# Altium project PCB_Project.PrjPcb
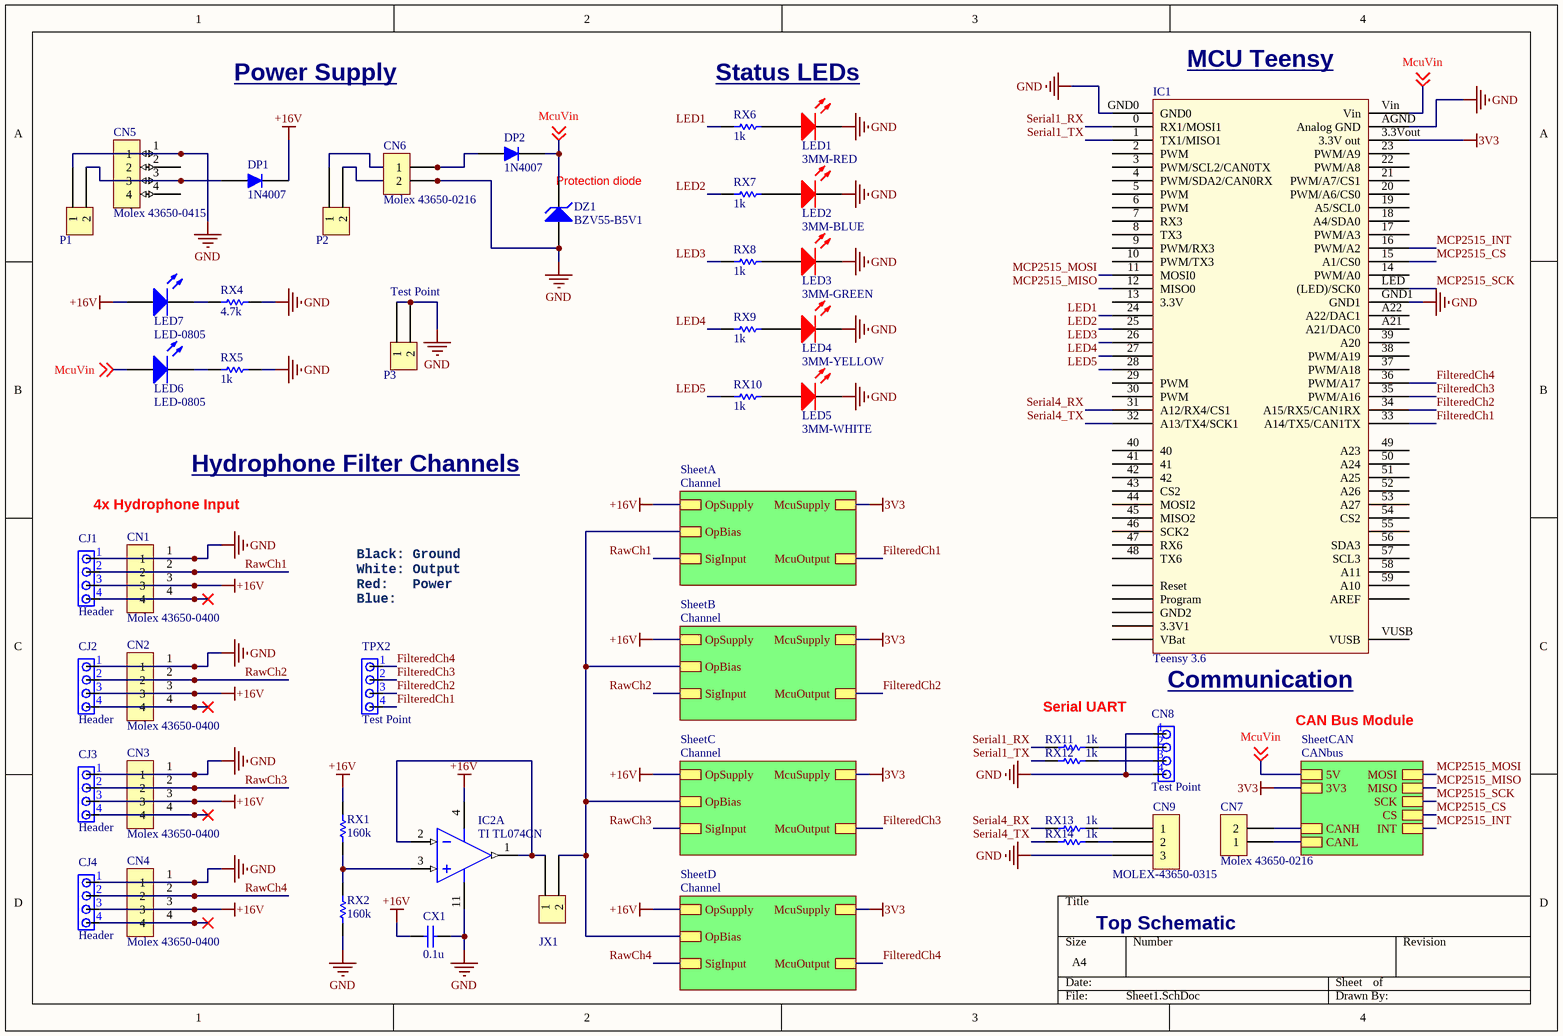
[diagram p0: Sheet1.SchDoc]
3 sheets, 286 parts. Net scope: hierarchical (ports join the sheet entries above them; power ports are global).
Sheets:
  Sheet1.SchDoc
    SheetA = Channel.SchDoc
    SheetB = Channel.SchDoc
    SheetC = Channel.SchDoc
    SheetD = Channel.SchDoc
    SheetCAN = CANbus.SchDoc

## Sheet Sheet1.SchDoc
size A4; SheetNumber: 1; SheetTotal: 3

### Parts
CJ1  Header  [PCB-0bfjvpkufifbx95u45yw-1]
CJ2  Header  [PCB-0bfjvpkufifbx95u45yw-1]
CJ3  Header  [PCB-0bfjvpkufifbx95u45yw-1]
CJ4  Header  [PCB-0bfjvpkufifbx95u45yw-1]
CN1  Molex 43650-0400  [PCB-jj5tynijxzvke4ihhisw-1]
CN2  Molex 43650-0400  [PCB-jj5tynijxzvke4ihhisw-1]
CN3  Molex 43650-0400  [PCB-jj5tynijxzvke4ihhisw-1]
CN4  Molex 43650-0400  [PCB-jj5tynijxzvke4ihhisw-1]
CN5  Molex 43650-0415  [PCB-vm2iqe32ix5ks50y5iwy-1]
CN6  Molex 43650-0216  [FP w/o mated connector outlined]
CN7  Molex 43650-0216  [FP w/o mated connector outlined]
CN8  Test Point  [PCB-0bfjvpkufifbx95u45yw-1]
CN9  MOLEX-43650-0315  [PCB-7ufjemrsb0p0f0we5rgt-1]
CX1  0.1u  [PCB-lqeomw61a722wi99q4vw-1]
DP1  1N4007  [PCBComponent_1]
DP2  1N4007  [PCBComponent_1]
DZ1  BZV55-B5V1  [PCB-lgxrfu0czqrr4p3mixw0-1]
IC1  Teensy 3.6  [PCB-6b281r67jm1h1mm3hlzb-1]
IC2  TI TL074CN  [PDIP-14]  (part A of 4)
JX1  Header 2pin  [PCB-header]  (value not drawn)
LED1  3MM-RED  [PCB-8fnm1gqdpse16arx63h0-1]
LED2  3MM-BLUE  [PCB-8fnm1gqdpse16arx63h0-1]
LED3  3MM-GREEN  [PCB-8fnm1gqdpse16arx63h0-1]
LED4  3MM-YELLOW  [PCB-8fnm1gqdpse16arx63h0-1]
LED5  3MM-WHITE  [PCB-8fnm1gqdpse16arx63h0-1]
LED6  LED-0805  [PCB-9ifma0oh53wy532w7hco-1]
LED7  LED-0805  [PCB-9ifma0oh53wy532w7hco-1]
P1  Header 2pin  [PCB-header]  (value not drawn)
P2  Header 2pin  [PCB-header]  (value not drawn)
P3  Test Point  [PCB-header]
RX1  160k  [RESC2013X70X40NL20T20]
RX2  160k  [RESC2013X70X40NL20T20]
RX4  4.7k  [RESC2013X70X40NL20T20]
RX5  1k  [RESC2013X70X40NL20T20]
RX6  1k  [RESC2013X70X40NL20T20]
RX7  1k  [RESC2013X70X40NL20T20]
RX8  1k  [RESC2013X70X40NL20T20]
RX9  1k  [RESC2013X70X40NL20T20]
RX10  1k  [RESC2013X70X40NL20T20]
RX11  1k  [RESC2013X70X40NL20T20]
RX12  1k  [RESC2013X70X40NL20T20]
RX13  1k  [RESC2013X70X40NL20T20]
RX14  1k  [RESC2013X70X40NL20T20]
TPX2  Test Point  [PCB-0bfjvpkufifbx95u45yw-1]

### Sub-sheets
SheetA = Channel: SigInput, OpSupply, OpBias, McuSupply, McuOutput
SheetB = Channel: SigInput, OpSupply, OpBias, McuSupply, McuOutput
SheetC = Channel: SigInput, OpSupply, OpBias, McuSupply, McuOutput
SheetCAN = CANbus: SCK, 3V3, CS, MISO, MOSI, 5V, CANL, CANH, INT
SheetD = Channel: SigInput, OpSupply, OpBias, McuSupply, McuOutput

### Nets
3V3: IC1.3.3Vout(3.3V_out) ; sheet SheetA/McuSupply, sheet SheetB/McuSupply, sheet SheetC/McuSupply, sheet SheetD/McuSupply, sheet SheetCAN/3V3  [project net 3V3_Supply]
+16V: CJ1.3 CJ2.3 CJ3.3 CJ4.3 CN1.3 CN2.3 CN3.3 CN4.3 CX1.1 DP1.2(K) IC2.4(VCC+) LED7.2(A) RX1.2 ; sheet SheetA/OpSupply, sheet SheetB/OpSupply, sheet SheetC/OpSupply, sheet SheetD/OpSupply  [project net OpSupply]
GND: CJ1.1 CJ2.1 CJ3.1 CJ4.1 CN1.1 CN2.1 CN3.1 CN4.1 CN5.1 CN6.2 CN8.1 CN8.4 CN9.3 CX1.2 DZ1.1(A) IC1.AGND(Analog_GND) IC1.GND0 IC1.GND1 IC2.11(VCC-) LED1.2(K) LED2.2(K) LED3.2(K) LED4.2(K) LED5.2(K) P1.1 P2.2 P3.1 P3.2 RX2.1 RX4.1 RX5.1
CAN_N: CN7.1 ; sheet SheetCAN/CANL
CAN_P: CN7.2 ; sheet SheetCAN/CANH
FilteredCh1: IC1.33(A14/TX5/CAN1TX) TPX2.4 ; sheet SheetA/McuOutput
FilteredCh2: IC1.34(A15/RX5/CAN1RX) TPX2.3 ; sheet SheetB/McuOutput
FilteredCh3: IC1.35(PWM/A16) TPX2.2 ; sheet SheetC/McuOutput
FilteredCh4: IC1.36(PWM/A17) TPX2.1 ; sheet SheetD/McuOutput
LED1: IC1.24 RX6.2
LED2: IC1.25 RX7.2
LED3: IC1.26 RX8.2
LED4: IC1.27 RX9.2
LED5: IC1.28 RX10.2
MCP2515_CS: IC1.15(A1/CS0) ; sheet SheetCAN/CS
MCP2515_INT: IC1.16(PWM/A2) ; sheet SheetCAN/INT
MCP2515_MISO: IC1.12(MISO0) ; sheet SheetCAN/MISO
MCP2515_MOSI: IC1.11(MOSI0) ; sheet SheetCAN/MOSI
MCP2515_SCK: IC1.LED((LED)/SCK0) ; sheet SheetCAN/SCK
McuVin: DP2.2(K) DZ1.2(K) IC1.Vin LED6.2(A) ; off-sheet McuVin, sheet SheetCAN/5V  [project net 5V_Supply]
OpBias: JX1.2 ; sheet SheetA/OpBias, sheet SheetB/OpBias, sheet SheetC/OpBias, sheet SheetD/OpBias
RawCh1: CJ1.2 CN1.2 ; sheet SheetA/SigInput
RawCh2: CJ2.2 CN2.2 ; sheet SheetB/SigInput
RawCh3: CJ3.2 CN3.2 ; sheet SheetC/SigInput
RawCh4: CJ4.2 CN4.2 ; sheet SheetD/SigInput
Serial1_RX: IC1.0(RX1/MOSI1) RX11.2
Serial1_TX: IC1.1(TX1/MISO1) RX12.2
Serial4_RX: IC1.31(A12/RX4/CS1) RX13.2
Serial4_TX: IC1.32(A13/TX4/SCK1) RX14.2
NetCJ1_4: CJ1.4 CN1.4
NetCJ2_4: CJ2.4 CN2.4
NetCJ3_4: CJ3.4 CN3.4
NetCJ4_4: CJ4.4 CN4.4
NetCN5_3: CN5.3 DP1.1(A) P1.2
NetCN6_1: CN6.1 DP2.1(A) P2.1
NetCN8_2: CN8.2 RX11.1
NetCN8_3: CN8.3 RX12.1
NetCN9_1: CN9.1 RX13.1
NetCN9_2: CN9.2 RX14.1
NetIC2_1: IC2.1(OUT1) IC2.2(IN1-) JX1.1
NetIC2_3: IC2.3(IN1+) RX1.1 RX2.2
NetLED1_1: LED1.1(A) RX6.1
NetLED2_1: LED2.1(A) RX7.1
NetLED3_1: LED3.1(A) RX8.1
NetLED4_1: LED4.1(A) RX9.1
NetLED5_1: LED5.1(A) RX10.1
NetLED6_1: LED6.1(K) RX5.2
NetLED7_1: LED7.1(K) RX4.2

Not connected (* = marked no-connect by the designer): CN5 2 4; IC1 2(PWM) 3(PWM/SCL2/CAN0TX) 3.3V1 4(PWM/SDA2/CAN0RX) 5(PWM) 6(PWM) 7(RX3) 8(TX3) 9(PWM/RX3) 10(PWM/TX3) 13(3.3V) 14(PWM/A0) 17(PWM/A3) 18(A4/SDA0) 19(A5/SCL0) 20(PWM/A6/CS0) 21(PWM/A7/CS1) 22(PWM/A8) 23(PWM/A9) 29(PWM) 30(PWM) 37(PWM/A18) 38(PWM/A19) 39(A20) 40 41 42 43(CS2) 44(MOSI2) 45(MISO2) 46(SCK2) 47(RX6) 48(TX6) 49(A23) 50(A24) 51(A25) 52(A26) 53(A27) 54(CS2) 55 56(SDA3) 57(SCL3) 58(A11) 59(A10) A21(A21/DAC0) A22(A22/DAC1) AREF GND2 Program Reset VBat VUSB

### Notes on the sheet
- Power Supply
- Status LEDs
- (near IC1) MCU Teensy
- (near DZ1) Protection
  diode
- 4x Hydrophone Input
- Hydrophone Filter Channels
- Black: Ground
  White: Output
  Red:   Power
  Blue:  Calibration
- Serial UART
- Communication
- CAN Bus Module
- Top Schematic

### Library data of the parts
CJ1-CJ4 CN8 TPX2 = CMP-ce480524f220118f-1: 5-146274-4 ; ROHS ; TYCO ; AMPMODU Breakaway Heade rs 4P HEADER TIN single r ow; ELV Compliant: Compliant
CN1-CN4 = CMP-2b85e28b82b9f442-5: Conn Power HDR 4 POS 3mm Solder RA Thru-Hole 4 Terminal 1 Port Micro-Fit 3.0????? Tray
CN5 = CMP-82ba4bb42b575d7d-1: Conn; Rect; Header; 4 Cir; PCB; MicroFit 3.0; Vertical; Single; SMT; w/Peg; Tin; Pin Pitch: 3.00 mm; Glow Wire Compliant: Compliant; Current Rating: 5.00 A; Number of Circuits: 4; Mated Height: 6.98 mm; Gender: Male
CN6 CN7 = CMP-0c70c57ea599d3b7-6: Conn Power HDR 2 POS 3mm Solder ST Thru-Hole 2 Terminal 1 Port Micro-Fit 3.0™ Tray; Voltage Rating (DC): 250 V; Mated Height: 17.3 mm; Gender: Male; Number of Positions: 2; Current Rating: 5.00 A; Pin Pitch: 3.00 mm; Lead-Free Status: Lead Free; Glow Wire Compliant: Compliant; Insulation Resistance: 1.00 GΩ
CN9 = CMP-of6dx0b68ulk1pyxyhr2-1
CX1 = CMP-773ebe35ab3ba8f9-5: Capacitor: ceramic; MLCC; 100nF; 50VDC; X7R; ±20%; SMD; 0805; MPN: C0805C104M5RACTU; Capacitance: 0.1 uF
DP1 DP2 = CMP-9114309-20: 1N4007 Series 1000 V 1 A Axial Lead Standard Recovery Rectifier - CASE 59-10; Manufacturer Part Number: 1N4007G; Voltage Rating (DC): 1.00 kV; Current Rating: 1.00 A; Forward Voltage: 1.10 V; Lead-Free Status: Lead Free; Output Current: 1.00 A (max); Breakdown Voltage: 1.00 kV (max)
DZ1 = CMP-ee91273a99d63156-2: BZV55 Series 5.1 V ±5 % 500 mW Surface Mount Voltage Regulator Diode - SOD-80C; Manufacturer Part Number: BZV55-C5V1,115; Lead-Free Status: Lead Free
IC1 = CMP-ff3832a4d40b20ff-34: Teensy 3.6 complete
IC2 = CMP-1321015-6: Quad Low-Noise JFET-Input General-Purpose Operational Amplifier, 7 to 36 V, DIP (N14); Manufacturer: Texas Instruments; Lead-Free Status: Lead Free; Slew Rate: 13.0 V/μs; Rise Time: 1e-07 s; Number of Channels: 4; Gain Bandwidth Product: 3000000.0 Hz; Supply Current: 0.0014 A; Input Bias Current: 6.5e-11 A; Model/Series: TL07x; Maximum Supply Voltage: 36VDC; Input Offset Drift: 1.8e-05 V/K
JX1 P1-P3 = CMP-74e0bf2ff245ab27-13: Connector, Through Hole, Header, 2, 2.54 mm 2pin; Manufacturer Part Number: 826926-2; ELV Compliant: Compliant; Pin Pitch: 2.54 mm; Gender: Male; Number of Contacts: 2; Lead-Free Status: Lead Free
LED1-LED5 = CMP-cd2f0425acb312e8-17: LED; Red; 30mcd; 0.126In.Dia.; T-1; 150mA; 2V; 635nm; 60deg; Diffused; 85 to 85degC; Manufacturer Part Number: SSL-LX3044LID; Forward Voltage: 2.00 V; Lead-Free Status: Lead Free; Viewing Angle: 60 °; Luminous Intensity: 30.0 mcd
LED6 LED7 = CMP-1071566-10: 598-8110-107F, Dialight, SMD LED 0805 Package, Red Single color SOLD IN INCREMENTS OF 4000. (REEL); Case/Package (SI): 2012; Wavelength: 635 nm, 642 nm; Luminous Intensity: 40.0 mcd; Forward Voltage: 2.20 V; Viewing Angle: 140 °; Lens Type: Non-Diffused; Lead-Free Status: Lead Free
RX1 RX2 RX4-RX14 = CMP-7553bc7ad099aa94-1: Res Thick Film 0805 100K Ohm 5% 1/8W ±200ppm/°C Molded SMD SMD Paper Tape on Plastic Reel; Manufacturer Part Number: CR0805-JW-104ELF; Case/Package (SI): 2012; Power Rating: 125 mW; Voltage Rating (DC): 150 V; Temperature Coefficient: -200 ppm/°C to 200 ppm/°C; Resistance: 100 kΩ

## Sheet Channel.SchDoc
size A3; SheetNumber: 2; SheetTotal: 3
Used 4 times, as channels SheetA, SheetB, SheetC, SheetD. Parts and nets are listed once, with the designators drawn on the sheet.
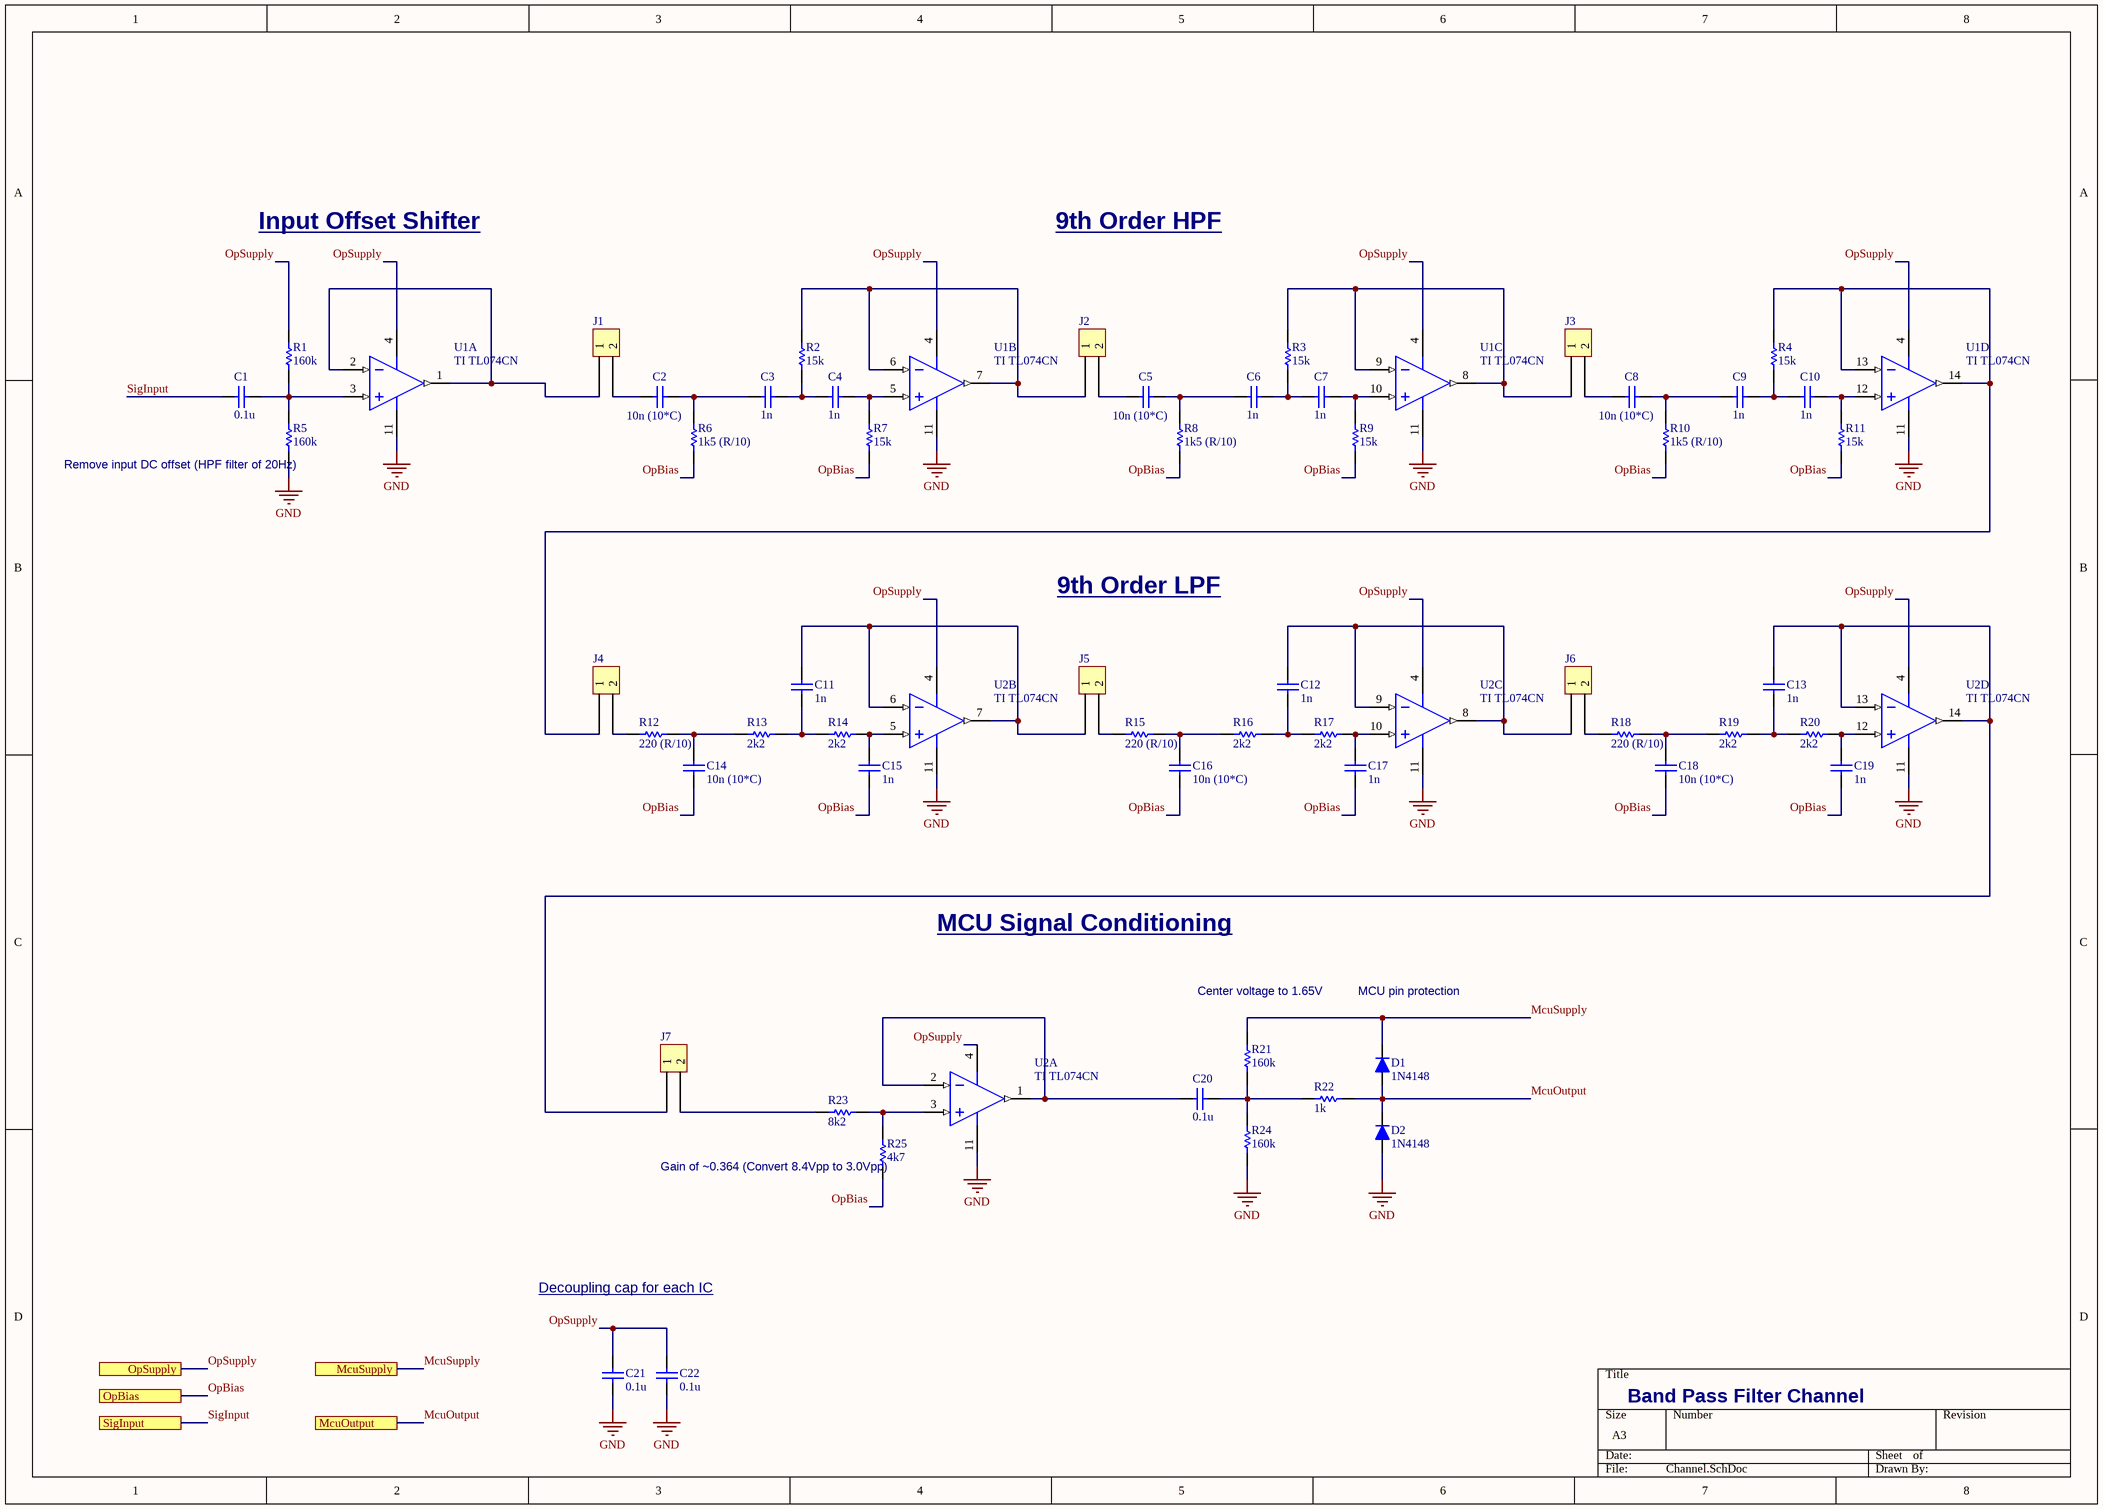
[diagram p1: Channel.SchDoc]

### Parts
C1  0.1u  [PCB-lqeomw61a722wi99q4vw-1]
C2  10n (10*C)  [PCB-lqeomw61a722wi99q4vw-1]
C3  1n  [PCB-lqeomw61a722wi99q4vw-1]
C4  1n  [PCB-lqeomw61a722wi99q4vw-1]
C5  10n (10*C)  [PCB-lqeomw61a722wi99q4vw-1]
C6  1n  [PCB-lqeomw61a722wi99q4vw-1]
C7  1n  [PCB-lqeomw61a722wi99q4vw-1]
C8  10n (10*C)  [PCB-lqeomw61a722wi99q4vw-1]
C9  1n  [PCB-lqeomw61a722wi99q4vw-1]
C10  1n  [PCB-lqeomw61a722wi99q4vw-1]
C11  1n  [PCB-lqeomw61a722wi99q4vw-1]
C12  1n  [PCB-lqeomw61a722wi99q4vw-1]
C13  1n  [PCB-lqeomw61a722wi99q4vw-1]
C14  10n (10*C)  [PCB-lqeomw61a722wi99q4vw-1]
C15  1n  [PCB-lqeomw61a722wi99q4vw-1]
C16  10n (10*C)  [PCB-lqeomw61a722wi99q4vw-1]
C17  1n  [PCB-lqeomw61a722wi99q4vw-1]
C18  10n (10*C)  [PCB-lqeomw61a722wi99q4vw-1]
C19  1n  [PCB-lqeomw61a722wi99q4vw-1]
C20  0.1u  [PCB-lqeomw61a722wi99q4vw-1]
C21  0.1u  [PCB-lqeomw61a722wi99q4vw-1]
C22  0.1u  [PCB-lqeomw61a722wi99q4vw-1]
D1  1N4148  [PCB-6o91fxjoj0j02yqh7kky-1]
D2  1N4148  [PCB-6o91fxjoj0j02yqh7kky-1]
J1  Header 2pin  [PCB-header]  (value not drawn)
J2  Header 2pin  [PCB-header]  (value not drawn)
J3  Header 2pin  [PCB-header]  (value not drawn)
J4  Header 2pin  [PCB-header]  (value not drawn)
J5  Header 2pin  [PCB-header]  (value not drawn)
J6  Header 2pin  [PCB-header]  (value not drawn)
J7  Header 2pin  [PCB-header]  (value not drawn)
R1  160k  [RESC2013X70X40NL20T20]
R2  15k  [RESC2013X70X40NL20T20]
R3  15k  [RESC2013X70X40NL20T20]
R4  15k  [RESC2013X70X40NL20T20]
R5  160k  [RESC2013X70X40NL20T20]
R6  1k5 (R/10)  [RESC2013X70X40NL20T20]
R7  15k  [RESC2013X70X40NL20T20]
R8  1k5 (R/10)  [RESC2013X70X40NL20T20]
R9  15k  [RESC2013X70X40NL20T20]
R10  1k5 (R/10)  [RESC2013X70X40NL20T20]
R11  15k  [RESC2013X70X40NL20T20]
R12  220 (R/10)  [RESC2013X70X40NL20T20]
R13  2k2  [RESC2013X70X40NL20T20]
R14  2k2  [RESC2013X70X40NL20T20]
R15  220 (R/10)  [RESC2013X70X40NL20T20]
R16  2k2  [RESC2013X70X40NL20T20]
R17  2k2  [RESC2013X70X40NL20T20]
R18  220 (R/10)  [RESC2013X70X40NL20T20]
R19  2k2  [RESC2013X70X40NL20T20]
R20  2k2  [RESC2013X70X40NL20T20]
R21  160k  [RESC2013X70X40NL20T20]
R22  1k  [RESC2013X70X40NL20T20]
R23  8k2  [RESC2013X70X40NL20T20]
R24  160k  [RESC2013X70X40NL20T20]
R25  4k7  [RESC2013X70X40NL20T20]
U1  TI TL074CN  [PDIP-14]  (parts A,B,C,D of 4)
U2  TI TL074CN  [PDIP-14]  (parts A,B,C,D of 4)

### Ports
McuOutput, McuSupply, OpBias, OpSupply, SigInput

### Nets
GND: C21.1 C22.1 D2.A R5.1 R24.1 U1.11(VCC-) U2.11(VCC-)
McuOutput: D1.A D2.K R22.1 ; port McuOutput
McuSupply: D1.K R21.2 ; port McuSupply
OpBias: C14.1 C15.1 C16.1 C17.1 C18.1 C19.1 R6.1 R7.1 R8.1 R9.1 R10.1 R11.1 R25.2 ; port OpBias
OpSupply: C21.2 C22.2 R1.2 U1.4(VCC+) U2.4(VCC+) ; port OpSupply
SigInput: C1.1 ; port SigInput
NetC1_2: C1.2 R1.1 R5.2 U1.3(IN1+)
NetC2_1: C2.1 J1.2
NetC2_2: C2.2 C3.1 R6.2
NetC3_2: C3.2 C4.1 R2.1
NetC4_2: C4.2 R7.2 U1.5(IN2+)
NetC5_1: C5.1 J2.2
NetC5_2: C5.2 C6.1 R8.2
NetC6_2: C6.2 C7.1 R3.1
NetC7_2: C7.2 R9.2 U1.10(IN3+)
NetC8_1: C8.1 J3.2
NetC8_2: C8.2 C9.1 R10.2
NetC9_2: C9.2 C10.1 R4.1
NetC10_2: C10.2 R11.2 U1.12(IN4+)
NetC11_1: C11.1 R13.1 R14.2
NetC11_2: C11.2 J5.1 U2.6(IN2-) U2.7(OUT2)
NetC12_1: C12.1 R16.1 R17.2
NetC12_2: C12.2 J6.1 U2.8(OUT3) U2.9(IN3-)
NetC13_1: C13.1 R19.1 R20.2
NetC13_2: C13.2 J7.1 U2.13(IN4-) U2.14(OUT4)
NetC14_2: C14.2 R12.1 R13.2
NetC15_2: C15.2 R14.1 U2.5(IN2+)
NetC16_2: C16.2 R15.1 R16.2
NetC17_2: C17.2 R17.1 U2.10(IN3+)
NetC18_2: C18.2 R18.1 R19.2
NetC19_2: C19.2 R20.1 U2.12(IN4+)
NetC20_1: C20.1 U2.1(OUT1) U2.2(IN1-)
NetC20_2: C20.2 R21.1 R22.2 R24.2
NetJ1_1: J1.1 U1.1(OUT1) U1.2(IN1-)
NetJ2_1: J2.1 R2.2 U1.6(IN2-) U1.7(OUT2)
NetJ3_1: J3.1 R3.2 U1.8(OUT3) U1.9(IN3-)
NetJ4_1: J4.1 R4.2 U1.13(IN4-) U1.14(OUT4)
NetJ4_2: J4.2 R12.2
NetJ5_2: J5.2 R15.2
NetJ6_2: J6.2 R18.2
NetJ7_2: J7.2 R23.1
NetR23_2: R23.2 R25.1 U2.3(IN1+)

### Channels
SheetA: designators C1=CA1 C2=CA2 C3=CA3 C4=CA4 C5=CA5 C6=CA6 C7=CA7 C8=CA8 C9=CA9 C10=CA10 C11=CA11 C12=CA12 C13=CA13 C14=CA14 C15=CA15 C16=CA16 C17=CA17 C18=CA18 C19=CA19 C20=CA20 C21=CA21 C22=CA22 D1=DA1 D2=DA2 J1=JA1 J2=JA2 J3=JA3 J4=JA4 J5=JA5 J6=JA6 J7=JA7 R1=RA1 R2=RA2 R3=RA3 R4=RA4 R5=RA5 R6=RA6 R7=RA7 R8=RA8 R9=RA9 R10=RA10 R11=RA11 R12=RA12 R13=RA13 R14=RA14 R15=RA15 R16=RA16 R17=RA17 R18=RA18 R19=RA19 R20=RA20 R21=RA21 R22=RA22 R23=RA23 R24=RA24 R25=RA25 U1=UA1 U2=UA2; ports McuOutput=FilteredCh1 McuSupply=3V3_Supply OpBias=OpBias OpSupply=OpSupply SigInput=RawCh1
SheetB: designators C1=CB1 C2=CB2 C3=CB3 C4=CB4 C5=CB5 C6=CB6 C7=CB7 C8=CB8 C9=CB9 C10=CB10 C11=CB11 C12=CB12 C13=CB13 C14=CB14 C15=CB15 C16=CB16 C17=CB17 C18=CB18 C19=CB19 C20=CB20 C21=CB21 C22=CB22 D1=DB1 D2=DB2 J1=JB1 J2=JB2 J3=JB3 J4=JB4 J5=JB5 J6=JB6 J7=JB7 R1=RB1 R2=RB2 R3=RB3 R4=RB4 R5=RB5 R6=RB6 R7=RB7 R8=RB8 R9=RB9 R10=RB10 R11=RB11 R12=RB12 R13=RB13 R14=RB14 R15=RB15 R16=RB16 R17=RB17 R18=RB18 R19=RB19 R20=RB20 R21=RB21 R22=RB22 R23=RB23 R24=RB24 R25=RB25 U1=UB1 U2=UB2; ports McuOutput=FilteredCh2 McuSupply=3V3_Supply OpBias=OpBias OpSupply=OpSupply SigInput=RawCh2
SheetC: designators C1=CC1 C2=CC2 C3=CC3 C4=CC4 C5=CC5 C6=CC6 C7=CC7 C8=CC8 C9=CC9 C10=CC10 C11=CC11 C12=CC12 C13=CC13 C14=CC14 C15=CC15 C16=CC16 C17=CC17 C18=CC18 C19=CC19 C20=CC20 C21=CC21 C22=CC22 D1=DC1 D2=DC2 J1=JC1 J2=JC2 J3=JC3 J4=JC4 J5=JC5 J6=JC6 J7=JC7 R1=RC1 R2=RC2 R3=RC3 R4=RC4 R5=RC5 R6=RC6 R7=RC7 R8=RC8 R9=RC9 R10=RC10 R11=RC11 R12=RC12 R13=RC13 R14=RC14 R15=RC15 R16=RC16 R17=RC17 R18=RC18 R19=RC19 R20=RC20 R21=RC21 R22=RC22 R23=RC23 R24=RC24 R25=RC25 U1=UC1 U2=UC2; ports McuOutput=FilteredCh3 McuSupply=3V3_Supply OpBias=OpBias OpSupply=OpSupply SigInput=RawCh3
SheetD: designators C1=CD1 C2=CD2 C3=CD3 C4=CD4 C5=CD5 C6=CD6 C7=CD7 C8=CD8 C9=CD9 C10=CD10 C11=CD11 C12=CD12 C13=CD13 C14=CD14 C15=CD15 C16=CD16 C17=CD17 C18=CD18 C19=CD19 C20=CD20 C21=CD21 C22=CD22 D1=DD1 D2=DD2 J1=JD1 J2=JD2 J3=JD3 J4=JD4 J5=JD5 J6=JD6 J7=JD7 R1=RD1 R2=RD2 R3=RD3 R4=RD4 R5=RD5 R6=RD6 R7=RD7 R8=RD8 R9=RD9 R10=RD10 R11=RD11 R12=RD12 R13=RD13 R14=RD14 R15=RD15 R16=RD16 R17=RD17 R18=RD18 R19=RD19 R20=RD20 R21=RD21 R22=RD22 R23=RD23 R24=RD24 R25=RD25 U1=UD1 U2=UD2; ports McuOutput=FilteredCh4 McuSupply=3V3_Supply OpBias=OpBias OpSupply=OpSupply SigInput=RawCh4

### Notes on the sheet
- Input Offset Shifter
- 9th Order HPF
- (near R5) Remove input DC offset
  (HPF filter of 20Hz)
- 9th Order LPF
- MCU Signal Conditioning
- (near R21) Center voltage
  to 1.65V
- MCU pin protection
- (near R25) Gain of ~0.364
  (Convert 8.4Vpp to 3.0Vpp)
- Decoupling cap for each IC
- Band Pass Filter Channel

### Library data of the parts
C1-C22 = CMP-773ebe35ab3ba8f9-5: as CX1 on sheet Sheet1
D1 D2 = CMP-59d690d966738611-1: Manufacturer Part Number: TMMBAT41FILM; Current Rating: 100 mA; Output Current: 100 mA (max); Voltage Rating (DC): 100 V; Lead-Free Status: Lead Free; Capacitance: 2.00 pF; Polarity: Standard
J1-J7 = CMP-74e0bf2ff245ab27-13: as JX1 on sheet Sheet1
R1-R25 = CMP-7553bc7ad099aa94-1: as RX1 on sheet Sheet1
U1 U2 = CMP-1321015-6: as IC2 on sheet Sheet1

## Sheet CANbus.SchDoc
size A4; SheetNumber: 3; SheetTotal: 3
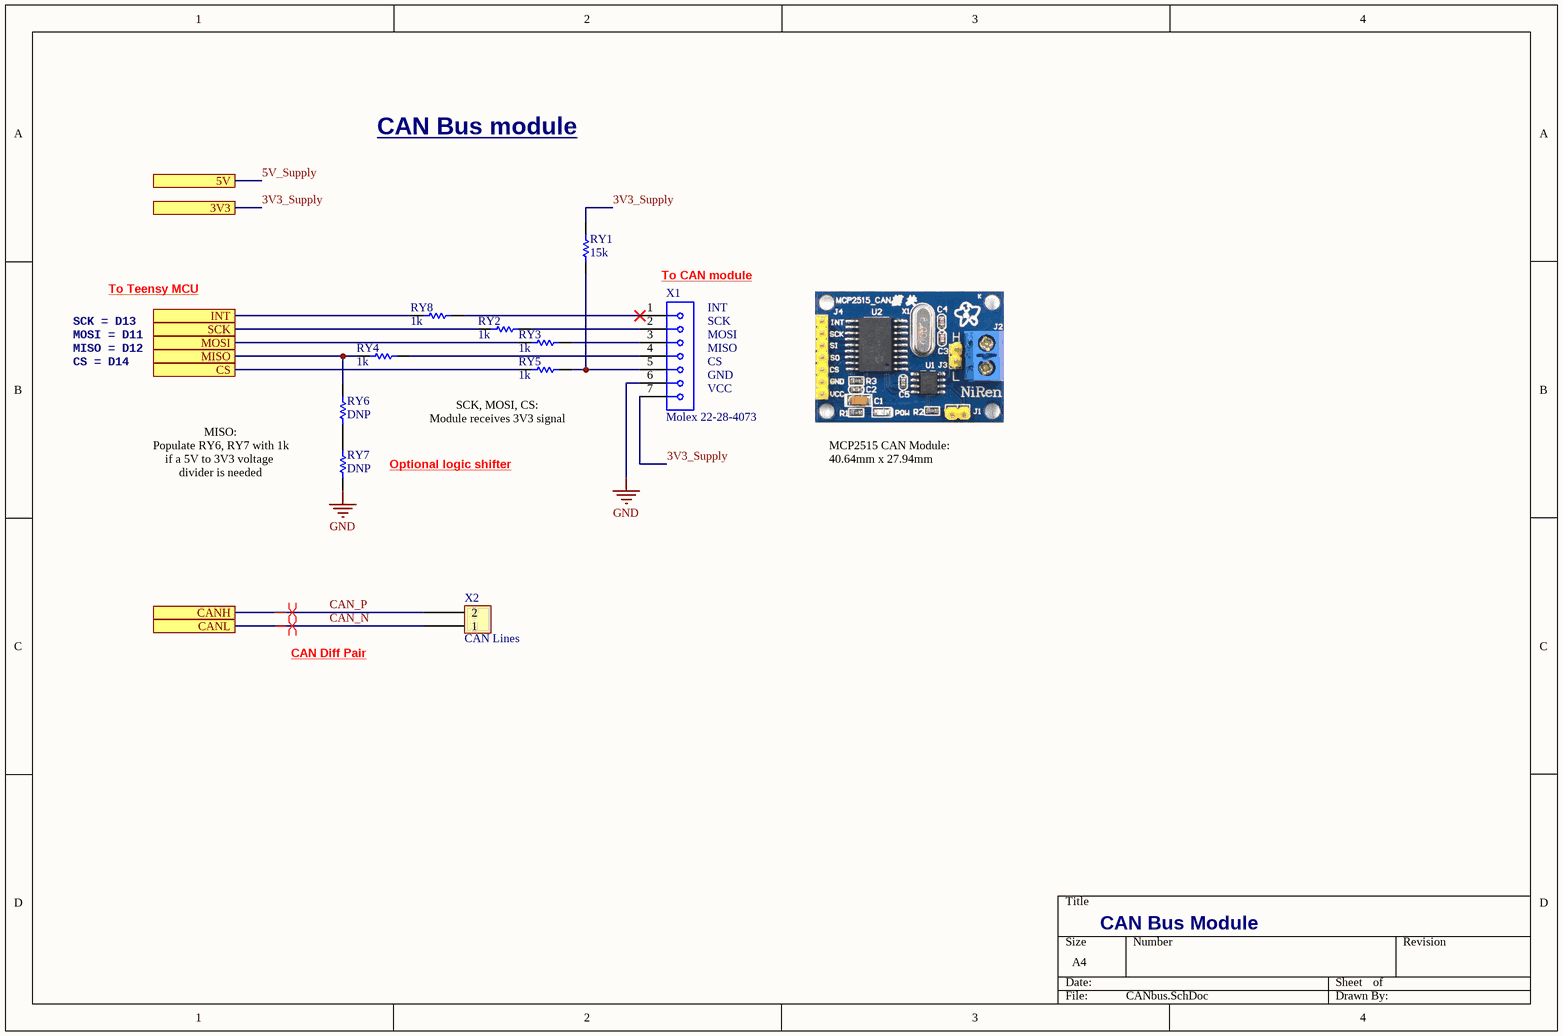
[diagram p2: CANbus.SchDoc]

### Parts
RY1  15k  [RESC2013X70X40NL20T20]
RY2  1k  [RESC2013X70X40NL20T20]
RY3  1k  [RESC2013X70X40NL20T20]
RY4  1k  [RESC2013X70X40NL20T20]
RY5  1k  [RESC2013X70X40NL20T20]
RY6  DNP  [RESC2013X70X40NL20T20]
RY7  DNP  [RESC2013X70X40NL20T20]
RY8  1k  [RESC2013X70X40NL20T20]
X1  Molex 22-28-4073  [HEADER_1x7]
X2  CAN Lines  [PCB-header]

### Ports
3V3, 5V, CANH, CANL, CS, INT, MISO, MOSI, SCK

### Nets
3V3_Supply: RY1.1 X1.7 ; port 3V3
GND: RY7.2 X1.6
CAN_N: X2.1 ; port CANL
CAN_P: X2.2 ; port CANH
MCP2515_CS: RY5.2 ; port CS
MCP2515_INT: RY8.2 ; port INT
MCP2515_MISO: RY4.2 RY6.1 ; port MISO
MCP2515_MOSI: RY3.2 ; port MOSI
MCP2515_SCK: RY2.2 ; port SCK
NetRY1_2: RY1.2 RY5.1 X1.5
NetRY2_1: RY2.1 X1.2
NetRY3_1: RY3.1 X1.3
NetRY4_1: RY4.1 X1.4
NetRY6_2: RY6.2 RY7.1
NetRY8_1: RY8.1 X1.1

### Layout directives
differential pair: CAN_N, CAN_P

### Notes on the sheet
- CAN Bus module
- To Teensy MCU
- (near X1) INT
- (near X1) To CAN module
- MOSI = D11
- MISO = D12
- CS = D14
- SCK = D13
- (near X1) SCK
- (near X1) MOSI
- (near X1) MISO
- (near X1) CS
- (near X1) GND
- (near RY5) SCK, MOSI, CS:
  Module receives 3V3 signal
- (near X1) VCC
- MISO:
  Populate RY6, RY7 with 1k
  if a 5V to 3V3 voltage
  divider is needed
- Optional logic shifter
- MCP2515 CAN Module:
  40.64mm x 27.94mm
- CAN Diff Pair
- CAN Bus Module

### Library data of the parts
RY1-RY8 = CMP-7553bc7ad099aa94-1: as RX1 on sheet Sheet1
X1 = CMP-42fc8bf259589d3b-3: Conn Unshrouded Header HDR 7 POS 2.54mm Solder ST Thru-Hole KKR Bag; Number of Circuits: 7; Glow Wire Compliant: Non-Compliant; Gender: Male; Voltage Rating (DC): 250 V; Lead-Free Status: Lead Free; Current Rating: 4.00 A
X2 = CMP-74e0bf2ff245ab27-13: as JX1 on sheet Sheet1

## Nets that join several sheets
3V3_Supply: Sheet1 (IC1.3.3Vout), SheetA (DA1.K RA21.2), SheetB (DB1.K RB21.2), SheetC (DC1.K RC21.2), SheetD (DD1.K RD21.2), CANbus (RY1.1 X1.7)
GND: Sheet1 (31 pins), SheetA (7 pins), SheetB (7 pins), SheetC (7 pins), SheetD (7 pins), CANbus (RY7.2 X1.6)
OpSupply: Sheet1 (13 pins), SheetA (5 pins), SheetB (5 pins), SheetC (5 pins), SheetD (5 pins)
CAN_N: Sheet1 (CN7.1), CANbus (X2.1)
CAN_P: Sheet1 (CN7.2), CANbus (X2.2)
FilteredCh1: Sheet1 (IC1.33 TPX2.4), SheetA (DA1.A DA2.K RA22.1)
FilteredCh2: Sheet1 (IC1.34 TPX2.3), SheetB (DB1.A DB2.K RB22.1)
FilteredCh3: Sheet1 (IC1.35 TPX2.2), SheetC (DC1.A DC2.K RC22.1)
FilteredCh4: Sheet1 (IC1.36 TPX2.1), SheetD (DD1.A DD2.K RD22.1)
MCP2515_CS: Sheet1 (IC1.15), CANbus (RY5.2)
MCP2515_INT: Sheet1 (IC1.16), CANbus (RY8.2)
MCP2515_MISO: Sheet1 (IC1.12), CANbus (RY4.2 RY6.1)
MCP2515_MOSI: Sheet1 (IC1.11), CANbus (RY3.2)
MCP2515_SCK: Sheet1 (IC1.LED), CANbus (RY2.2)
OpBias: Sheet1 (JX1.2), SheetA (13 pins), SheetB (13 pins), SheetC (13 pins), SheetD (13 pins)
RawCh1: Sheet1 (CJ1.2 CN1.2), SheetA (CA1.1)
RawCh2: Sheet1 (CJ2.2 CN2.2), SheetB (CB1.1)
RawCh3: Sheet1 (CJ3.2 CN3.2), SheetC (CC1.1)
RawCh4: Sheet1 (CJ4.2 CN4.2), SheetD (CD1.1)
